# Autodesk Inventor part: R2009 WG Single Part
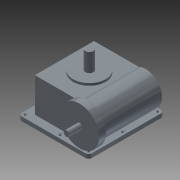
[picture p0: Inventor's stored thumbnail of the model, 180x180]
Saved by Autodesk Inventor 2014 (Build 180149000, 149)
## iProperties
Created: 2007-07
Part Number: R2009 WG Single Part
Document SubType Name: Modeling
Designer: normanpa
Density: 1 g/cm^3
Material: Generic
Appearance: Zinc
Author: normanpa
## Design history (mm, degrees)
sketch "Sketch1"
  geometry: L1 (0, 0)-(330, 0); L2 (0, 210)-(0, 0); L3 (330, 0)-(330, 20.723); L4 (0, 210)-(274.411, 210); A1 r 100 centre (318, 120) between (330, 20.723) and (274.411, 210); 1 further point
  constraints: 8 end point, 2 perpendicular, 2 point on circle, 1 centre point, 1 horizontal, 1 parallel, 1 other
  dimensions: "d0" = 210 distance of L2.start L1.start; "d1" = 330 distance of L1.start L1.end (= 2 x d5); "d2" = 200 diameter of A1; "d3" = 120 distance from line of L1 A1.centre; "d4" = 12 distance from line of L3 A1.centre
extrude "Extrusion1" new body sketch "Sketch1" distance "d6" = 363; taper "d7" = 0 deg
sketch "Sketch2"
  geometry: L1 (330, 363)-(0, 363) reference; L2 (0, 0)-(0, 363) reference; L3 (0, 0)-(330, 0) reference; L4 (330, 0)-(330, 363) reference; L5 (380, 413)-(-50, 413); L6 (-50, 413)-(-50, -50); L7 (-50, -50)-(380, -50); L8 (380, -50)-(380, 413)
  constraints: 8 end point, 3 other
  dimensions: "d8" = 50 distance between parallel lines of L1 L5
extrude "Extrusion2" join sketch "Sketch2" distance "d9" = 25; taper "d10" = 0 deg
sketch "Sketch3"
  geometry: L1 (318, 36.3)-(318, -471.9); L2 (274.411, 0)-(0, 0); L3 (0, -363)-(274.411, -363); L4 (274.411, 0)-(274.411, -363); L5 (0, 0)-(0, -363); C1 r 100 at (153, -181.5)
  constraints: 10 end point, 1 centre point
  dimensions: "d11" = 200 diameter of C1; "d12" = 165 distance from line of C1.centre L1; "d13" = 181.5 distance from line of C1.centre L2 (= 0.5 x d14)
extrude "Extrusion3" join sketch "Sketch3" distance "d15" = 14; taper "d16" = 0 deg
sketch "Sketch4"
  geometry: C1 r 100 at (0, 0) reference; C2 r 25 at (0, 0); 1 further point
  constraints: 1 centre point, 1 coincident
  dimensions: "d17" = 50 diameter of C2
extrude "Extrusion4" join sketch "Sketch4" distance "d18" = 112; taper "d19" = 0 deg
sketch "Sketch5"
  geometry: C1 r 119 at (318, 120); A1 r 100 centre (318, 120) between (330, 20.723) and (274.411, 210) reference
  constraints: 1 centre point, 1 coincident
  dimensions: "d20" = 238 diameter of C1
extrude "Extrusion5" join sketch "Sketch5" distance "d21" = 43; taper "d22" = 0 deg
sketch "Sketch6"
  geometry: C1 r 119 at (0, 0) reference; C2 r 17.5 at (0, 0); 1 further point
  constraints: 1 centre point, 1 coincident
  dimensions: "d23" = 35 diameter of C2
extrude "Extrusion6" join sketch "Sketch6" distance "d24" = 80.5; taper "d25" = 0 deg
fillet "Fillet1" dims "d26" = 20
sketch "Sketch7"
  geometry: A1 r 20 centre (-30, 30) between (-30, 50) and (-50, 30) reference; A2 r 20 centre (-30, -393) between (-50, -393) and (-30, -413) reference; A3 r 20 centre (360, -393) between (360, -413) and (380, -393) reference; A4 r 20 centre (360, 30) between (380, 30) and (360, 50) reference; 4 further points
  constraints: 3 horizontal alignment, 3 vertical alignment
  dimensions: "d27" = 215.5 distance of point (-30, -185.5) A1.centre; "d28" = 215 distance of point (185, 30) A1.centre
hole "Hole1" sketch "Sketch7" at (-30, -185.5), (360, -185.5), (185, -393), (185, 30), (-30, 30), (-30, -393), (360, 30), (360, -393) diameter "d29" = 12; stored, may be unused: countersink angle "d33" = 90 deg, drill point angle "d35" = 118 deg; dims "d30" = 6, "d31" = 25, "d32" = 1.25, "d34" = 8
body "Solid1"
other parameters: "d5" = 165, "d14" = 363 (= 2.2 x d12)
